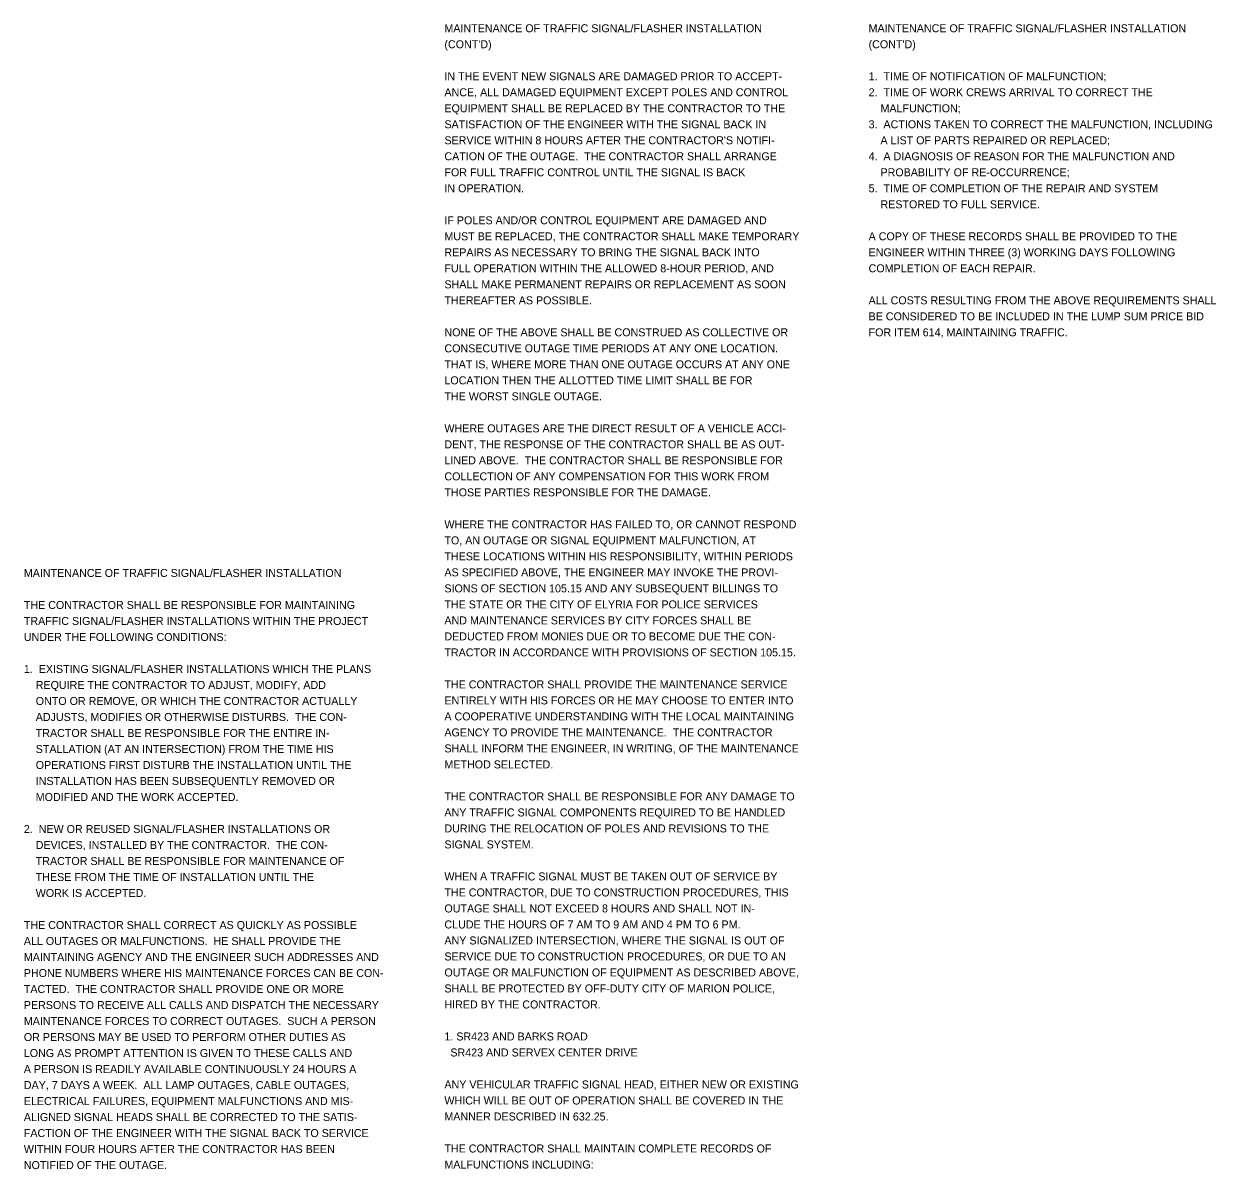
# Model space of a CAD drawing. Extents: x 0 to 71.8, y 0 to 22.
# Drawn here: x 50.97 to 71.83, y 1.11 to 21.15 of the extents above; entities that cross this region are included whole.
import ezdxf

# ---------------------------------------------------------------- set-up
doc = ezdxf.new("R2010")
doc.units = 0
doc.layers.add('SH_Text', color=7, linetype='Continuous')

msp = doc.modelspace()

# ---------------------------------------------------------------- texts
at = {"layer": 'SH_Text'}
for s, p in [('MAINTENANCE OF TRAFFIC SIGNAL/FLASHER INSTALLATION', (58.328, 21)), ('MAINTENANCE OF TRAFFIC SIGNAL/FLASHER INSTALLATION', (65.748, 21)), ("(CONT'D)", (58.328, 20.72)), ("(CONT'D)", (65.748, 20.72)), ('IN THE EVENT NEW SIGNALS ARE DAMAGED PRIOR TO ACCEPT-', (58.328, 20.16)), ('1.  TIME OF NOTIFICATION OF MALFUNCTION;', (65.748, 20.16)), ('ANCE, ALL DAMAGED EQUIPMENT EXCEPT POLES AND CONTROL', (58.328, 19.88)), ('2.  TIME OF WORK CREWS ARRIVAL TO CORRECT THE', (65.748, 19.88)), ('EQUIPMENT SHALL BE REPLACED BY THE CONTRACTOR TO THE', (58.328, 19.6)), ('    MALFUNCTION;', (65.748, 19.6)), ('SATISFACTION OF THE ENGINEER WITH THE SIGNAL BACK IN', (58.328, 19.32)), ('3.  ACTIONS TAKEN TO CORRECT THE MALFUNCTION, INCLUDING', (65.748, 19.32)), ("SERVICE WITHIN 8 HOURS AFTER THE CONTRACTOR'S NOTIFI-", (58.328, 19.04)), ('    A LIST OF PARTS REPAIRED OR REPLACED;', (65.748, 19.04)), ('CATION OF THE OUTAGE.  THE CONTRACTOR SHALL ARRANGE', (58.328, 18.76)), ('4.  A DIAGNOSIS OF REASON FOR THE MALFUNCTION AND', (65.748, 18.76)), ('FOR FULL TRAFFIC CONTROL UNTIL THE SIGNAL IS BACK', (58.328, 18.48)), ('    PROBABILITY OF RE-OCCURRENCE;', (65.748, 18.48)), ('IN OPERATION.', (58.328, 18.2)), ('5.  TIME OF COMPLETION OF THE REPAIR AND SYSTEM', (65.748, 18.2)), ('    RESTORED TO FULL SERVICE.', (65.748, 17.92)), ('IF POLES AND/OR CONTROL EQUIPMENT ARE DAMAGED AND', (58.328, 17.64)), ('MUST BE REPLACED, THE CONTRACTOR SHALL MAKE TEMPORARY', (58.328, 17.36)), ('A COPY OF THESE RECORDS SHALL BE PROVIDED TO THE', (65.748, 17.36)), ('REPAIRS AS NECESSARY TO BRING THE SIGNAL BACK INTO', (58.328, 17.08)), ('ENGINEER WITHIN THREE (3) WORKING DAYS FOLLOWING', (65.748, 17.08)), ('FULL OPERATION WITHIN THE ALLOWED 8-HOUR PERIOD, AND', (58.328, 16.8)), ('COMPLETION OF EACH REPAIR.', (65.748, 16.8)), ('SHALL MAKE PERMANENT REPAIRS OR REPLACEMENT AS SOON', (58.328, 16.52)), ('THEREAFTER AS POSSIBLE.', (58.328, 16.24)), ('ALL COSTS RESULTING FROM THE ABOVE REQUIREMENTS SHALL', (65.748, 16.24)), ('BE CONSIDERED TO BE INCLUDED IN THE LUMP SUM PRICE BID', (65.748, 15.96)), ('NONE OF THE ABOVE SHALL BE CONSTRUED AS COLLECTIVE OR', (58.328, 15.68)), ('FOR ITEM 614, MAINTAINING TRAFFIC.', (65.748, 15.68)), ('CONSECUTIVE OUTAGE TIME PERIODS AT ANY ONE LOCATION.', (58.328, 15.4)), ('THAT IS, WHERE MORE THAN ONE OUTAGE OCCURS AT ANY ONE', (58.328, 15.12)), ('LOCATION THEN THE ALLOTTED TIME LIMIT SHALL BE FOR', (58.328, 14.84)), ('THE WORST SINGLE OUTAGE.', (58.328, 14.56)), ('WHERE OUTAGES ARE THE DIRECT RESULT OF A VEHICLE ACCI-', (58.328, 14)), ('DENT, THE RESPONSE OF THE CONTRACTOR SHALL BE AS OUT-', (58.328, 13.72)), ('LINED ABOVE.  THE CONTRACTOR SHALL BE RESPONSIBLE FOR', (58.328, 13.44)), ('COLLECTION OF ANY COMPENSATION FOR THIS WORK FROM', (58.328, 13.16)), ('THOSE PARTIES RESPONSIBLE FOR THE DAMAGE.', (58.328, 12.88)), ('WHERE THE CONTRACTOR HAS FAILED TO, OR CANNOT RESPOND', (58.328, 12.32)), ('TO, AN OUTAGE OR SIGNAL EQUIPMENT MALFUNCTION, AT', (58.328, 12.04)), ('THESE LOCATIONS WITHIN HIS RESPONSIBILITY, WITHIN PERIODS', (58.328, 11.76)), ('MAINTENANCE OF TRAFFIC SIGNAL/FLASHER INSTALLATION', (50.971, 11.47)), ('AS SPECIFIED ABOVE, THE ENGINEER MAY INVOKE THE PROVI-', (58.328, 11.48)), ('SIONS OF SECTION 105.15 AND ANY SUBSEQUENT BILLINGS TO', (58.328, 11.2)), ('THE STATE OR THE CITY OF ELYRIA FOR POLICE SERVICES', (58.328, 10.92)), ('THE CONTRACTOR SHALL BE RESPONSIBLE FOR MAINTAINING', (50.971, 10.91)), ('TRAFFIC SIGNAL/FLASHER INSTALLATIONS WITHIN THE PROJECT', (50.971, 10.63)), ('AND MAINTENANCE SERVICES BY CITY FORCES SHALL BE', (58.328, 10.64)), ('UNDER THE FOLLOWING CONDITIONS:', (50.971, 10.35)), ('DEDUCTED FROM MONIES DUE OR TO BECOME DUE THE CON-', (58.328, 10.36)), ('TRACTOR IN ACCORDANCE WITH PROVISIONS OF SECTION 105.15.', (58.328, 10.08)), ('1.  EXISTING SIGNAL/FLASHER INSTALLATIONS WHICH THE PLANS', (50.971, 9.79)), ('    REQUIRE THE CONTRACTOR TO ADJUST, MODIFY, ADD', (50.971, 9.51)), ('THE CONTRACTOR SHALL PROVIDE THE MAINTENANCE SERVICE', (58.328, 9.52)), ('    ONTO OR REMOVE, OR WHICH THE CONTRACTOR ACTUALLY', (50.971, 9.23)), ('ENTIRELY WITH HIS FORCES OR HE MAY CHOOSE TO ENTER INTO', (58.328, 9.24)), ('    ADJUSTS, MODIFIES OR OTHERWISE DISTURBS.  THE CON-', (50.971, 8.95)), ('A COOPERATIVE UNDERSTANDING WITH THE LOCAL MAINTAINING', (58.328, 8.96)), ('    TRACTOR SHALL BE RESPONSIBLE FOR THE ENTIRE IN-', (50.971, 8.67)), ('AGENCY TO PROVIDE THE MAINTENANCE.  THE CONTRACTOR', (58.328, 8.68)), ('    STALLATION (AT AN INTERSECTION) FROM THE TIME HIS', (50.971, 8.39)), ('SHALL INFORM THE ENGINEER, IN WRITING, OF THE MAINTENANCE', (58.328, 8.4)), ('    OPERATIONS FIRST DISTURB THE INSTALLATION UNTIL THE', (50.971, 8.11)), ('METHOD SELECTED.', (58.328, 8.12)), ('    INSTALLATION HAS BEEN SUBSEQUENTLY REMOVED OR', (50.971, 7.83)), ('    MODIFIED AND THE WORK ACCEPTED.', (50.971, 7.55)), ('THE CONTRACTOR SHALL BE RESPONSIBLE FOR ANY DAMAGE TO', (58.328, 7.56)), ('ANY TRAFFIC SIGNAL COMPONENTS REQUIRED TO BE HANDLED', (58.328, 7.28)), ('2.  NEW OR REUSED SIGNAL/FLASHER INSTALLATIONS OR', (50.971, 6.99)), ('DURING THE RELOCATION OF POLES AND REVISIONS TO THE', (58.328, 7)), ('    DEVICES, INSTALLED BY THE CONTRACTOR.  THE CON-', (50.971, 6.71)), ('SIGNAL SYSTEM.', (58.328, 6.72)), ('    TRACTOR SHALL BE RESPONSIBLE FOR MAINTENANCE OF', (50.971, 6.43)), ('    THESE FROM THE TIME OF INSTALLATION UNTIL THE', (50.971, 6.15)), ('WHEN A TRAFFIC SIGNAL MUST BE TAKEN OUT OF SERVICE BY', (58.328, 6.16)), ('    WORK IS ACCEPTED.', (50.971, 5.87)), ('THE CONTRACTOR, DUE TO CONSTRUCTION PROCEDURES, THIS', (58.328, 5.88)), ('OUTAGE SHALL NOT EXCEED 8 HOURS AND SHALL NOT IN-', (58.328, 5.6)), ('THE CONTRACTOR SHALL CORRECT AS QUICKLY AS POSSIBLE', (50.971, 5.31)), ('CLUDE THE HOURS OF 7 AM TO 9 AM AND 4 PM TO 6 PM.', (58.328, 5.32)), ('ALL OUTAGES OR MALFUNCTIONS.  HE SHALL PROVIDE THE', (50.971, 5.03)), ('ANY SIGNALIZED INTERSECTION, WHERE THE SIGNAL IS OUT OF ', (58.328, 5.04)), ('MAINTAINING AGENCY AND THE ENGINEER SUCH ADDRESSES AND', (50.971, 4.75)), ('SERVICE DUE TO CONSTRUCTION PROCEDURES, OR DUE TO AN ', (58.328, 4.76)), ('PHONE NUMBERS WHERE HIS MAINTENANCE FORCES CAN BE CON-', (50.971, 4.47)), ('OUTAGE OR MALFUNCTION OF EQUIPMENT AS DESCRIBED ABOVE,', (58.328, 4.48)), ('TACTED.  THE CONTRACTOR SHALL PROVIDE ONE OR MORE', (50.971, 4.19)), ('SHALL BE PROTECTED BY OFF-DUTY CITY OF MARION POLICE,', (58.328, 4.2)), ('PERSONS TO RECEIVE ALL CALLS AND DISPATCH THE NECESSARY', (50.971, 3.91)), ('HIRED BY THE CONTRACTOR.', (58.328, 3.92)), ('MAINTENANCE FORCES TO CORRECT OUTAGES.  SUCH A PERSON', (50.971, 3.63)), ('OR PERSONS MAY BE USED TO PERFORM OTHER DUTIES AS', (50.971, 3.35)), ('1. SR423 AND BARKS ROAD', (58.328, 3.36)), ('LONG AS PROMPT ATTENTION IS GIVEN TO THESE CALLS AND', (50.971, 3.07)), ('  SR423 AND SERVEX CENTER DRIVE', (58.328, 3.08)), ('A PERSON IS READILY AVAILABLE CONTINUOUSLY 24 HOURS A', (50.971, 2.79)), ('DAY, 7 DAYS A WEEK.  ALL LAMP OUTAGES, CABLE OUTAGES,', (50.971, 2.51)), ('ANY VEHICULAR TRAFFIC SIGNAL HEAD, EITHER NEW OR EXISTING', (58.328, 2.52)), ('ELECTRICAL FAILURES, EQUIPMENT MALFUNCTIONS AND MIS-', (50.971, 2.23)), ('WHICH WILL BE OUT OF OPERATION SHALL BE COVERED IN THE', (58.328, 2.24)), ('ALIGNED SIGNAL HEADS SHALL BE CORRECTED TO THE SATIS-', (50.971, 1.95)), ('MANNER DESCRIBED IN 632.25.', (58.328, 1.96)), ('FACTION OF THE ENGINEER WITH THE SIGNAL BACK TO SERVICE', (50.971, 1.67)), ('WITHIN FOUR HOURS AFTER THE CONTRACTOR HAS BEEN', (50.971, 1.39)), ('THE CONTRACTOR SHALL MAINTAIN COMPLETE RECORDS OF', (58.328, 1.4)), ('NOTIFIED OF THE OUTAGE.', (50.971, 1.11)), ('MALFUNCTIONS INCLUDING:', (58.328, 1.12))]:
    msp.add_text(s, height=0.14, dxfattribs=at).set_placement(p)

doc.saveas('drawing.dxf')
